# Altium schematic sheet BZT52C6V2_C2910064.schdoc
size 127 x 101 mm
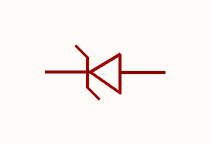
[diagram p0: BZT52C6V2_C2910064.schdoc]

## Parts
U?  bzt52c6v2_c2910064  [SOD-123_L2.7-W1.6-LS3.7-RD]  (value not drawn)

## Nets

Not connected (* = marked no-connect by the designer): U? 1(C) 2(A)

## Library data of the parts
U? = bzt52c6v2_c2910064: 二极管配置:1个独立式;稳压值(标称值):6.2V;稳压值(范围):5.8V~6.6V;耗散功率(Pd):500mW;; Manufacturer: CJ(江苏长电/长晶); AddInBom: yes; ModelId: ad7e39f9e5534b3c96ffdc5532ebb493; ModelName: SOD-123_L2.7-W1.6-H1.4-LS3.7; ModelTransform: 146.026,62.992,0,180,0,0,0.0005,0,0; Diode Configuration: 1个独立式; Zener Voltage(Nom): 6.2V; Reverse Leakage Current (Ir): 3uA@4V; Pd - Power Dissipation: 500mW; Impedance(Zzt): 10Ω; Impedance(Zzk): 150Ω; Operating Junction Temperature Range: -55℃~+150℃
